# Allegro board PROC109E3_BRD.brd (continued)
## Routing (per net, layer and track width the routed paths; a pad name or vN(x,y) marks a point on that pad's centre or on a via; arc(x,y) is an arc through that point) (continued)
VSYS_3V3_CT: length 2.7
  BOTTOM w0.254: U27.4 17.24,58.7 C81.1
VSYS_3V3_FB: length 4.4
  TOP w0.254: U10.2 43.93,42.61 43.92,42.61 43.92,41.17 R77.1 R80.2 C40.2
VSYS_3V3_R: length 3.9
  TOP w0.508: 48.11,50.16 48.38,49.89 R35.2 48.38,48.38 47.6,47.6 C26.1
VSYS_3V3_SENSE: length 6.2
  BOTTOM w0.135: U27.9 19.8,53.58 20.35,53.04 20.35,51.44 21.3,50.48 R201.1 R195.1
VSYS_3V3_SW: length 4.8
  TOP w0.254: U10.6 44.43,45.08 44.85,45.51
  TOP w0.762: 44.85,45.51 L1.1
VSYS_5V0: length 100.5
  TOP w0.254: U21.7 49.64,30.4 C51.1 ; 32.72,23.7 32.7,23.69 U23.8 ; C25.1 43.93,45.64 U10.7 ; U23.7 32.78,23.19
  TOP w0.305: 122.6,43.45 122.17,43.02 C123.1 121.56,42.47 v1(121.36,42.27)
  TOP w0.381: R11.1 v1(12.05,55.71) ; R85.2 43.11,38.55 v1(43.18,38.48) ; v1(16.54,49.48) 17.11,48.9 17.11,41.17 15.57,39.62 12.7,39.62 11.68,40.64 8.64,40.64 6.73,38.73 R86.1 ; R117.1 34.97,24.99 v1(34.54,24.56)
  TOP w0.508: U14.1 50.36,38.72 49.94,39.14 ; v1(100.5,15.2) R161.2 v1(99.69,16)
  TOP w0.762: J9.1 137.27,15.11 131.34,21.03 129.08,21.03 127.36,22.76 127.36,40.41 124.32,43.45 122.6,43.45
  BOTTOM w0.203: U33.4 121.62,42.01 v1(121.36,42.27)
  BOTTOM w0.254: U27.14 16.24,51.05 16.38,50.91 C91.1 16.38,49.63 v1(16.54,49.48) ; v1(146.89,12.47) C269.1 146.26,12.47 U46.15
  BOTTOM w0.33: v1(163.42,22.66) R270.1 v1(164.19,23.46) ; v1(65.53,23.24) 65.56,23.27 R262.1
  BOTTOM w0.381: v1(16.54,49.48) 15.14,48.08 13.64,48.08 13.09,47.53 12.36,47.53 12.07,47.24 R211.2 ; v1(23.27,52.11) 23.2,52.04 R188.1 ; R171.2 9.28,58.49 v1(12.05,55.71)
  BOTTOM w0.508: R281.1 v1(152.98,14.38) ; R280.1 v1(154.79,14.38) ; R272.1 v1(156.51,20.73) ; R279.1 v1(156.51,14.38) ; R274.1 v1(152.98,20.73) ; R273.1 v1(154.79,20.73)
  vias: v1(32.26,24.59) v1(33.27,24.56) v1(33.27,23.6) v1(34.54,23.6) v1(35.89,24.56) v1(35.89,23.6) v1(35.92,22.66) v1(37.16,24.56) v1(37.16,23.6) v1(37.19,22.66) v1(39.98,48.64) v1(39.98,47.37) v1(39.98,46.1) v1(39.98,44.83) v1(41.25,48.64) v1(41.25,47.37) v1(41.25,46.1) v1(41.25,44.83) v1(42.52,48.64) v1(42.52,47.37) v1(42.52,46.1) v1(42.52,44.83) v1(45.7,33.35) v1(45.7,32.08) v1(45.7,30.81) v1(45.7,29.54) v1(46.84,37.03) v1(46.89,39.57) v1(46.86,38.48) v1(46.97,33.35) v1(46.97,32.08) v1(46.97,30.81) v1(46.97,29.54) v1(48.16,39.57) v1(48.24,33.35) v1(48.24,32.08) v1(48.24,30.81) v1(48.24,29.54)
VSYS_5V0_CT: length 2.4
  TOP w0.203: U23.6 32.75,22.69 33.02,22.42 C69.1
VSYS_5V0_ON: length 33.6
  TOP w0.254: v1(28.93,22.61) 29.01,22.68 29.06,22.68 29.06,22.69 U23.3 ; v1(17.15,34.17) LD9.1 16.54,34.8 16.27,35.06 U15.4
  L03_SIG1 w0.203: v1(28.93,22.61) 24.08,22.61 23.39,23.29 23.39,26.21 22.81,26.8 14.73,26.8 13.87,27.66 13.87,34.54 14.71,35.38 15.94,35.38 v1(17.15,34.17)
VUSB_5V0: length 55.4
  TOP w0.135: v1(15.12,27.46) 23.04,27.46 24.21,26.29
  TOP w0.178: 10.26,27.79 U20.12
  TOP w0.254: U15.5 15.91,36.06 16.07,36.22 C42.1 ; U23.2 29.04,23.19 28.88,23.34 ; 10.26,27.79 10.21,27.84 C57.1 9.3,28.37 v1(9.3,28.42) ; 28.42,23.14 28.42,22.31 28.68,22.06 29.07,22.06 29.2,22.19 U23.4 ; U23.1 29.02,23.69
  TOP w0.33: v1(17.27,36.22) 16.56,36.22 C42.1 ; R110.2 15.12,30.15 14.79,30.48 v1(14.63,30.48)
  TOP w0.381: R113.2 v1(15.12,27.46) ; v1(4.34,26.8) 4.29,26.75 v1(3.07,26.75) v1(1.8,26.75) ; v1(10.19,31.57) 10.55,31.94 R105.2 R106.2 ; v1(17.27,36.22) 17.71,35.78 R94.1
  L03_SIG1 w0.508: v1(9.3,28.42) 9.3,30.68 v1(10.19,31.57)
  L04_PWR1 w0.381: v1(17.27,36.22) 12.29,36.22 10.19,34.11 v1(10.19,31.57)
  L04_PWR1 w0.508: v1(4.34,26.8) 7.67,26.8 v1(9.3,28.42)
  BOTTOM w0.33: C226.1 3.81,27.3
  BOTTOM w0.381: v1(15.12,27.46) 14.63,27.95 v1(14.63,30.48) 11.28,30.48 v1(10.19,31.57)
WDI: length 3.1
  TOP w0.135: R9.2 v1(13.84,56.62)
  BOTTOM w0.135: U27.20 13.97,55.08 13.84,55.21 v1(13.84,56.62)
WDO: length 2.3
  TOP w0.135: R11.2 13.09,54.51 v1(13.49,54.12)
  BOTTOM w0.135: U27.19 13.95,54.58 v1(13.49,54.12)
XDS110_DEBUG_ID4: length 3.7
  TOP w0.135: R98.1 v1(20.5,30.51)
  BOTTOM w0.135: v1(20.5,30.51) 21.21,29.79 21.21,29.01 21.1,28.9 U37.63
XDS110_DEBUG_ID5: length 3.6
  TOP w0.135: R99.1 v1(22.05,30.51)
  BOTTOM w0.135: U37.62 21.5,29.96 v1(22.05,30.51)
XDS110_DEBUG_ID6: length 4.3
  TOP w0.135: R100.1 v1(23.52,30.51)
  BOTTOM w0.135: U37.61 21.9,29.34 23.07,30.51 v1(23.52,30.51)
XDS110_DEBUG_ID7: length 5.3
  TOP w0.135: R101.1 v1(24.99,30.51)
  BOTTOM w0.135: v1(24.99,30.51) 24.46,29.97 23.11,29.97 22.3,29.16 U37.60
XDS110_EMU0: length 7.8
  TOP w0.135: U16.8 28.51,33.64 29.06,33.1 29.06,30.06 29.26,29.86 R109.1 v1(29.84,29.18)
  BOTTOM w0.135: U37.42 29.5,29.05 29.64,29.18 v1(29.84,29.18)
XDS110_EMU1: length 12.2
  TOP w0.135: U16.1 31.62,33.64 32.03,33.23 32.03,29.03 31.5,28.5 29.06,28.5 v1(28.37,29.18) R108.1
  BOTTOM w0.135: v1(28.37,29.18) 28.93,29.18 29.1,29.01 U37.43
XDS110_PROG_STAZ1: length 35.2
  TOP w0.135: R114.2 v1(6.5,27.58)
  L03_SIG1 w0.121: v1(33.38,40.69) 32.57,39.88 20.29,39.88 19.43,39.01 16.18,39.01 7.16,30 7.16,28.24 v1(6.5,27.58)
  BOTTOM w0.135: v1(33.38,40.69) 34.6,40.69 U37.4
XDS110_PROG_STAZ2: length 36.8
  TOP w0.135: v1(6.25,30.58) 5.82,30.16 R111.2
  L03_SIG1 w0.121: v1(35.83,41.09) 35.74,41.17 33.12,41.17 32.09,40.14 19.92,40.14 19.05,39.27 14.69,39.27 8.61,33.19 8.61,32.94 v1(6.25,30.58)
  BOTTOM w0.135: v1(35.83,41.09) 35.82,41.09 U37.3
XDS110_TCK: length 44.4
  TOP w0.135: v1(70.33,24.21) 70.04,23.91 U25.13
  L03_SIG1 w0.121: v1(70.33,24.21) 69.91,24.62 68.52,24.62 67.23,25.91 66.31,25.91 64.62,27.6 64.62,28.41 62.22,30.8 50.66,30.8 48.9,29.04 32.91,29.04 v1(32.79,29.16)
  BOTTOM w0.135: U37.35 32.3,28.91 32.56,29.16 v1(32.79,29.16)
XDS110_TDI: length 49.3
  TOP w0.135: U25.12 v1(70.69,21.01)
  L03_SIG1 w0.121: v1(70.69,21.01) 70.69,21.72 69.52,22.89 68.97,22.89 64.34,27.52 64.34,28.33 62.81,29.86 50.18,29.86 48.09,27.77 39.29,27.77 38.76,28.3 31.65,28.3 v1(30.76,29.18)
  BOTTOM w0.135: U37.38 31.1,28.84 v1(30.76,29.18)
XDS110_TDO: length 50.6
  L03_SIG1 w0.121: v1(30.76,30.1) 30,30.1 29.18,29.29 29.18,26.54 29.59,26.14 30.17,26.14 30.45,26.42 30.45,26.95 31.16,27.66 37.42,27.66 38.39,26.69 44.13,26.69 45.04,25.78 59.59,25.78 60.78,24.59 v1(60.78,21.34)
  BOTTOM w0.135: U42.7 65.52,20.57 65.27,20.32 64.43,20.32 64.14,20.32 63.11,21.34 v1(60.78,21.34) ; U37.37 31.5,29.36 v1(30.76,30.1)
XDS110_TMS: length 46.8
  TOP w0.135: v1(71.48,24.23) 71.34,24.09 U25.11
  L03_SIG1 w0.121: v1(71.48,24.23) 70.74,24.97 68.63,24.97 67.34,26.26 66.32,26.26 64.87,27.71 64.87,28.51 62.33,31.06 50.21,31.06 49.28,30.12 45.11,30.12 44.28,29.3 33.49,29.3 v1(32.72,30.07)
  BOTTOM w0.135: U37.36 31.9,29.26 v1(32.72,30.07)
XDS110_TRST#: length 53.3
  TOP w0.135: U25.10 71.99,21.56 v1(72.01,21.54)
  L03_SIG1 w0.121: v1(72.01,21.54) 70.87,20.4 70,20.4 69.26,21.14 69.26,22.18 64.06,27.38 64.06,28.24 62.7,29.6 50.58,29.6 47.48,26.5 44.82,26.5 44.12,27.2 38.31,27.2 37.59,27.91 30.48,27.91 29.92,27.36 v1(29.92,26.64)
  BOTTOM w0.135: v1(29.92,26.64) 30.3,27.03 U37.40
XDS110_UART1_RXD: length 17.6
  L03_SIG1 w0.121: v1(39.65,23.77) 39.65,24.77 37.67,26.75 v1(33.88,26.75)
  BOTTOM w0.135: v1(39.65,23.77) 39.65,22.94 38.51,21.8 34.57,21.8 34.28,21.51 U45.13 ; v1(33.88,26.75) 33.33,26.75 33.1,26.98 U37.33
XDS110_UART1_TXD: length 17.6
  L03_SIG1 w0.121: v1(32.72,26.44) 32.87,26.29 37.57,26.29 38.38,25.48 v1(38.38,23.85)
  BOTTOM w0.135: U45.11 32.98,21.48 33.58,22.07 37.74,22.07 38.38,22.71 v1(38.38,23.85) ; v1(32.72,26.44) 32.7,26.45 U37.34
XDS110_VBUS_DET: length 21
  L03_SIG1 w0.121: v1(28.57,41.94) 24.82,45.69 v1(18.29,45.69)
  BOTTOM w0.135: v1(28.57,41.94) 29.11,41.4 33.1,41.4 33.58,41.89 U37.1
  BOTTOM w0.508: v1(18.29,45.69) 17.58,46.41 R212.1 R219.2
XDS_RBIAS: length 2.6
  BOTTOM w0.178: U37.59 22.7,26.83 23.05,26.48 23.05,25.71 R256.1
XDS_RESET#: length 6
  TOP w0.135: v1(17.73,33.43) 15.93,33.43 TP26.1
  BOTTOM w0.135: R246.2 v1(17.73,33.43) 17.73,31.88 18.12,31.49 U37.70
XDS_SHIELD:
  vias: v1(4.85,16.05) v1(4.85,14.78) v1(6.12,16.05) v1(6.12,14.78) v1(7.39,16.05) v1(7.39,14.78)
XDS_USB_D_N: length 35.3
  TOP w0.107: J20.2 6.52,21.73 6.73,21.52 7.59,21.52 7.73,21.66 U24.4 U24.7 9.5,21.66 9.64,21.52 10.06,21.52 v1(10.4,21.86)
  L03_SIG1 w0.102: v1(10.4,21.86) 10.73,21.53 11.27,21.53 12.24,22.51 12.24,34.34 14.5,36.6 15.85,36.6 16.73,37.49 17.22,37.49 17.75,38.02 18.36,38.02 18.9,37.49 20.47,37.49 20.86,37.89 20.86,38.67 v1(20.52,39.01)
  BOTTOM w0.107: U37.93 20.07,40.69 20.15,40.77 20.42,40.77 20.96,40.23 20.96,38.82 20.85,38.71 20.63,38.71 20.52,38.82 v1(20.52,39.01)
XDS_USB_D_P: length 35.3
  TOP w0.107: J20.3 6.52,21.08 6.73,21.29 7.59,21.29 7.73,21.16 U24.5 U24.6 9.5,21.16 9.64,21.29 10.06,21.29 v1(10.4,20.95)
  L03_SIG1 w0.102: v1(21.46,39.01) 21.12,38.67 21.12,37.78 20.57,37.24 18.79,37.24 18.26,37.77 17.86,37.77 17.33,37.24 16.84,37.24 15.95,36.35 14.61,36.35 12.5,34.24 12.5,22.4 11.37,21.28 10.73,21.28 v1(10.4,20.95)
  BOTTOM w0.107: v1(21.46,39.01) 21.19,39.29 21.19,40.33 20.52,41 20.1,41 20.02,41.09 U37.94
XDS_USB_ID: length 32.3
  TOP w0.135: U24.9 v1(9.66,22.66)
  TOP w0.178: v1(7.47,22.3) 7.82,22.66 U24.2 U24.9
  TOP w0.254: J20.4 v1(6.89,20.43)
  L03_SIG1 w0.121: v1(9.66,22.66) 8.71,23.61 8.71,26.21 7.87,27.05 6.1,27.05 5.56,27.58 5.56,30.68 14.25,39.37 v1(14.25,40.82)
  L03_SIG1 w0.127: v1(6.89,20.43) 7.47,21.01 v1(7.47,22.3)
  BOTTOM w0.135: R231.2 14.82,40.94 14.7,40.82 v1(14.25,40.82)
XDS_VREF: length 5.9
  BOTTOM w0.178: C129.1 36.63,38.69 U37.9
  BOTTOM w0.33: C129.1 C128.1 38.1,38.63
  BOTTOM w0.381: U36.3 39.64,39.13 39.38,38.88 R235.2 38.65,38.63 38.1,38.63
N17247526: length 1.4
  TOP w0.135: LD15.2 v1(175.98,8.43)
  BOTTOM w0.135: R282.2 v1(175.98,8.43)
N17247539: length 1.4
  TOP w0.135: LD14.2 v1(174.48,8.43)
  BOTTOM w0.135: R283.2 v1(174.48,8.43)
N17247599: length 1.4
  TOP w0.135: LD13.2 v1(172.98,8.43)
  BOTTOM w0.135: R284.2 v1(172.98,8.43)
N17247637: length 1.4
  TOP w0.135: LD12.2 v1(171.48,8.43)
  BOTTOM w0.135: R285.2 v1(171.48,8.43)
N29126233: length 2.6
  TOP w0.135: R67.1 24.79,44.32 24.16,44.96 SW4.11
N29126235: length 2.5
  TOP w0.135: SW4.12 24.18,46.23 24.59,45.82 R53.1
N29126237: length 2.4
  TOP w0.135: SW4.13 24.41,47.5 24.59,47.32 R48.1
N29126239: length 2.3
  TOP w0.135: SW4.14 24.41,48.77 24.46,48.82 R34.1
N29126243: length 2.7
  TOP w0.135: SW4.10 24,43.69 24.87,42.82 R70.1
N29126245: length 2.4
  TOP w0.135: SW4.15 24.46,50.04 24.74,50.32 R28.1
N29126269: length 2.5
  TOP w0.135: SW4.16 24.93,51.31 25.4,51.78 R17.1
N30174920: length 3.2
  BOTTOM w0.135: R179.2 R180.2 76.56,53.06 76.69,52.93 U31.2
N30212600: length 7.4
  TOP w0.135: LD2.1 165.76,61.47 164.78,60.48 v1(163.84,60.48)
  BOTTOM w0.135: Q5.2 Q5.1 ; Q5.1 163.84,59.18 Q5.8 163.84,58.53 Q5.6 Q5.5 ; Q5.1 v1(163.84,60.48)
N30212640: length 1.3
  TOP w0.135: v1(167.34,64.04) 167.34,63.4 LD1.2
  BOTTOM w0.135: R167.2 v1(167.34,64.04)
N30212699: length 7
  TOP w0.135: v1(168.66,60.48) 168.12,60.48 167.32,61.28 LD1.1
  BOTTOM w0.135: Q6.2 Q6.1 ; Q6.1 v1(168.66,60.48) ; Q6.1 168.66,59.18 Q6.8 168.66,58.53 Q6.6 Q6.5
N30213674: length 1.3
  TOP w0.135: v1(165.77,64.05) 165.77,63.41 LD2.2
  BOTTOM w0.135: v1(165.77,64.05) 165.77,63.39 R166.2
N30217069: length 3.6
  BOTTOM w0.178: U37.96 17.82,41.89 17.57,42.14 C114.1
  BOTTOM w0.33: C114.1 17.1,42.51 17.31,42.72 R222.1
N30217074: length 2.1
  BOTTOM w0.135: R231.1 17.85,41.49 U37.95
N30217111: length 1.4
  TOP w0.135: LD10.2 R111.1
N30217160: length 1.4
  TOP w0.135: LD11.2 R114.1
N30310219: length 2.7
  TOP w0.381: D3.3 35.95,28.29 R117.2 R118.1
N30339679: length 27.9
  TOP w0.135: R15.1 13.82,53.26 v1(14.71,52.37) 20.4,52.37 21.79,53.77 22.84,53.77 24,52.6 24.73,52.6 25.16,53.03 26.29,53.03 27.46,54.2 27.46,54.81 30,57.36 30,58.31 29.73,58.59 U1.1
  BOTTOM w0.135: v1(14.71,52.37) 14.18,52.37 13.84,52.71 13.84,53.82 14.1,54.08 U27.18 ; v1(14.71,52.37) 15.05,52.03 U27.15 ; v1(14.71,52.37) 14.69,52.39 U27.16
N30360253: length 14.6
  TOP w0.135: v1(143.37,24.84) 142.87,24.84 142.68,25.02 U19.48 ; TP25.1 142.68,34.75 v1(142.68,33.4) U19.13
  BOTTOM w0.135: v1(142.68,33.4) 140.69,31.41 140.69,26.57 142.42,24.84 v1(143.37,24.84)
N30371240: length 3.5
  BOTTOM w0.135: R258.2 180.75,35.6 J19.11
N30391563: length 2.3
  BOTTOM w0.135: R210.2 J18.11
N30391831: length 14
  TOP w0.135: U7.13 v1(142.68,52.45) 142.68,53.8 TP4.1 ; U7.48 142.68,43.98 142.8,43.87 v1(143.33,43.87)
  BOTTOM w0.135: v1(142.68,52.45) 140.77,50.54 140.77,46.43 v1(143.33,43.87)
N30573184: length 1.3
  TOP w0.135: R79.2 LD6.2
N30625746: length 12.9
  TOP w0.102: U18.B5 77.11,27.58 76.55,27.58 76.2,27.24
  TOP w0.135: 76.2,27.24 75.86,26.9 75.86,26.26 73.38,23.77 73.38,20.95 v1(72.36,19.94)
  BOTTOM w0.135: R271.2 v1(72.36,19.94)
N30693218: length 2.2
  TOP w0.135: v1(174.83,61.32) 174.81,61.33 LD3.3
  BOTTOM w0.135: R168.2 174.83,62.64 v1(174.83,61.32)
N30693408: length 2.8
  TOP w0.135: v1(172.62,61.34) 172.63,61.33 LD3.2
  BOTTOM w0.135: R169.2 173.63,61.87 173.09,61.34 v1(172.62,61.34)
N30703604: length 1.3
  TOP w0.135: LD7.2 R86.2
N30811240: length 7.9
  TOP w0.135: v1(175.58,60.14) 175.34,60.38 175.34,62.36 174.76,62.93 LD3.4
  BOTTOM w0.135: v1(175.58,60.14) Q9.5 Q9.6 176.23,58.87 Q9.8 175.9,58.5 176.23,58.17 Q9.1 Q9.2
N30811389: length 5.6
  TOP w0.135: v1(172.81,64.12) 173.27,63.66 LD3.1
  BOTTOM w0.135: Q4.2 Q4.1 172.06,62.82 Q4.8 172.06,63.47 Q4.6 ; Q4.6 v1(172.81,64.12) ; Q4.6 Q4.5
N30900913: length 6.5
  TOP w0.102: 76.05,32.86 U18.A15
  TOP w0.135: v1(72.7,33.03) 72.88,32.86 76.05,32.86
  BOTTOM w0.135: v1(72.7,33.03) 72.7,33.73 R244.1 72.7,35.08 R240.1
N30979572: length 1.8
  TOP w0.135: R162.2 70.31,16.18 70.04,16.45 U25.4
N31410611: length 1.3
  TOP w0.135: R91.2 LD8.2
N31410626: length 4.8
  TOP w0.135: Q3.2 Q3.1 1.71,34.09 Q3.8 1.71,34.74 Q3.6 ; Q3.6 1.71,35.89 1.72,35.9 LD8.1 ; Q3.6 Q3.5
N31458583: length 2.4
  TOP w0.135: R119.2 13.59,26.72 13.39,26.93 13.39,27.4 13,27.79 U20.3
N31483389: length 1.3
  TOP w0.254: LD9.2 R94.2
N32041451: length 3.1
  TOP w0.254: R31.2 58.05,49.98 58.48,49.54 U5.4

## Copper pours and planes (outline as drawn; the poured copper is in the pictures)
DGND on L03_SIG1 (solid shape): 168.03,13.81 168.09,13.9 168.2,13.88 169.97,12.12 169.97,11.59 169.9,11.5 169.79,11.52 168.03,13.28
DGND on L03_SIG1 (solid shape): 77.11,22.57 77.22,22.59 77.28,22.5 77.28,20.45 77.89,19.84 77.89,19.72 77.83,19.72 77.82,19.73 77.62,19.75 77.43,19.67 77.36,19.64 77.29,19.67 77.06,19.91 77.06,22.51
DGND on L03_SIG1 (solid shape): 12.92,34.16 12.97,34.17 13,34.12 13,28.87 13.46,28.41 13.46,27.49 14.56,26.39 15.47,26.39 15.56,26.33 15.54,26.22 13.02,23.7 13.02,22.66 12.94,22.57 12.88,22.56 12.85,22.61 12.85,34.09
DGND on L03_SIG1 (solid shape): 82.28,24.76 82.34,24.85 82.45,24.83 83.38,23.9 83.38,19.41 84.38,18.41 85.32,18.41 85.39,18.38 85.43,18.31 85.43,18.27 85.44,18.23 85.42,18.14 85.34,18.1 84.53,18.1 82.28,20.35
DGND on L03_SIG1 (solid shape): 141.67,30.89 141.67,27.13 139.5,24.96 139.5,24.95 139.34,24.78 139.31,24.54 139.29,24.46 139.21,24.42 139.14,24.42 139.03,24.4 138.97,24.49 138.97,24.97 138.06,25.88 138.06,31.04 138.33,31.31 141.25,31.31
DGND on L03_SIG1 (solid shape): 12.01,19.42 12.12,19.44 12.18,19.34 12.18,18.31 13.56,16.94 13.58,16.83 13.48,16.76 12.8,16.76 12.17,16.14 12.17,8.88 12.71,8.34 12.73,8.23 12.63,8.17 11.01,8.16 9.09,10.08 9.09,17.32 8.39,18.03 8.37,18.14 8.46,18.2 10.79,18.2
DGND on L03_SIG1 (solid shape): 65.24,28.09 65.3,28.18 65.41,28.16 65.66,27.91 65.97,27.91 66.04,27.88 66.07,27.82 66.32,27.48 66.73,27.58 66.8,27.61 66.87,27.58 68.54,25.91 68.57,25.83 68.53,25.76 68.51,25.74 68.44,25.71 68.37,25.74 67.49,26.63 66.47,26.63 65.24,27.86
DGND on L03_SIG1 (solid shape): 27.92,16.48 27.98,16.57 28.09,16.55 30.67,13.97 30.67,9.09 31.44,8.32 38.2,8.32 39.24,9.36 64.87,9.36 65.88,8.35 65.91,8.24 65.81,8.18 65.56,8.18 65.48,8.22 65.46,8.31 65.1,8.81 64.74,8.31 64.73,8.22 64.64,8.18 27.47,8.18 27.38,8.24 27.4,8.35 27.92,8.87
DGND on L03_SIG1 (solid shape): 22.46,21.94 22.52,22.03 22.63,22.01 26.82,17.83 26.84,17.72 26.75,17.65 24.16,17.65 23.6,17.1 23.6,16.76 21.81,16.76 21.23,16.18 21.2,16.2 20.86,16.27 20.56,16.13 20.52,16.12 20.49,16.13 20.39,16.2 20.27,16.25 20.24,16.28 20.24,16.31 20.01,16.89 19.4,16.86 19.36,16.9 19.33,16.98 19.36,17.05 20.16,17.86 20.56,17.86 20.56,17.86 21.69,17.86 22.46,18.63
DGND on L03_SIG1 (solid shape): 78.82,13.87 78.92,13.79 78.88,13.68 77.35,11.09 78.6,8.36 78.63,8.25 78.54,8.18 72.55,8.18 71.68,8.81 70.81,8.18 66.78,8.18 66.69,8.22 66.68,8.31 66.68,8.57 66.51,8.76 66.5,8.77 66.36,8.9 66.34,9.02 66.44,9.08 69.01,9.08 70.6,10.67 70.71,10.69 70.77,10.6 72.33,10 71.73,11.56 71.64,11.62 71.66,11.73 73.79,13.87
DGND on L03_SIG1 (solid shape): outline of 406 points within 68.09,15.87 78.44,26.09
DGND on TOP: 50.8,46.28 50.68,46.16 50.68,45.78 50.5,45.6 49.77,45.6 49.76,45.59 46.97,45.59 46.59,45.97 46.59,46.86 46.33,47.12 45.83,47.12 45.7,46.99 45.7,45.21 45.06,45.21 44.68,44.83 44.68,43.82 44.57,43.7 39.63,43.7 39.37,43.43 39.37,40.77 39.62,40.51 42.42,40.51 42.86,40.96 42.86,42.73 43.31,43.18 44.35,43.18 44.35,40.84 44.56,40.64 45.49,40.64 46.2,41.35 53.39,41.35 53.8,41.76 53.8,45.8 53.31,46.28
DGND on TOP: 48.74,36.88 49.57,36.88 50.14,37.45 55.36,37.45 55.5,37.59 55.5,37.91 55.32,38.09 54.83,38.09 54.82,38.08 50.02,38.08 49.53,37.59 48.76,37.59 48.67,37.5 48.67,36.96
DGND on TOP: 100.22,55.34 97.99,55.34 97.79,55.54 97.79,56.92 97.97,57.1 100.2,57.1 100.31,56.99 100.31,55.43
DGND on TOP: 74.68,40.52 74.68,39.97 75.19,39.45 75.53,39.45 76.48,38.51 76.48,38.14 76.65,37.97 76.87,37.97 76.96,38.06 76.96,39.8 76.24,40.52
DGND on TOP: 4.85,19.89 4.85,19.27 5.56,18.56 7.63,18.56 8.36,17.83 10.19,17.83 10.46,18.11 10.46,19.8 10.17,20.09 5.05,20.09
DGND on TOP: 72.95,39.87 72.95,37.63 73.37,37.21 74.78,37.21 76.76,35.23 77.06,35.23 77.52,35.69 77.52,35.94 77.01,36.45 76.71,36.45 74.69,38.47 74.26,38.47 73.52,39.21 73.52,39.87
DGND on TOP: 110.81,53.16 118.7,53.16 119.32,52.55 119.32,46.3 118.79,45.77 110.92,45.77 110.43,46.26 110.43,52.78 ; 1 cut-out
DGND on BOTTOM: 78.03,26.44 78.12,26.34 78.12,23.9 78.29,23.74 78.29,22.31 78.23,22.25 76.45,22.25 76.17,22.53 76.17,25.29 77.32,26.44
DGND on BOTTOM: 86.33,34.34 89.03,34.34 89.23,34.14 89.63,34.14 89.74,34.03 89.74,33.57 89.73,33.56 89.73,32.96 89.48,32.72 88.75,32.72 88.44,33.02 88.44,33.32 88.29,33.48 86.64,33.48 86.31,33.15 86.26,33.15 85.78,33.63 85.78,33.78
DGND on BOTTOM: 31.11,13.74 33.78,13.74 33.96,13.92 33.96,16.31 34.39,16.74 38.33,16.74 38.46,16.86 38.46,18.36 38.35,18.47 36.37,18.47 35.86,18.97 35.86,20.8 35.7,20.97 31.63,20.97 30.35,22.25 24.76,22.25 24.26,21.74 24.26,16.55 24.65,16.15 28.7,16.15
DGND on BOTTOM: 83.69,32.56 83.69,31.7 83.79,31.6 84.96,31.6 85.24,31.88 85.24,32.05 85.12,32.18 85.12,32.87 85.04,32.94 84.73,32.94 84.61,32.82 84.61,32.69 84.53,32.61 83.74,32.61
DGND on BOTTOM: 37.67,38.28 37.92,38.02 37.92,37.39 37.67,37.13 35.76,37.13 35.66,37.24 35.66,38.2 35.74,38.28
DGND on BOTTOM: 127.95,36.45 129.41,36.45 129.67,36.7 129.67,40.45 129.48,40.64 127.66,40.64 127.52,40.5 127.52,39.92 127.15,39.55 127.15,39.16 127.75,38.57 127.75,36.64
DGND on BOTTOM: 11.39,33.44 12.43,33.44 12.84,33.03 12.84,30.99 12.97,30.86 14.61,30.86 14.78,31.03 14.78,31.4 14.66,31.53 13.5,31.53 13.39,31.65 13.39,33.99 13.21,34.16 11.44,34.16 11.24,33.97 11.24,33.59
DGND on BOTTOM: 86.12,35.82 86.76,36.47 89.05,36.47 89.36,36.78 89.36,39.04 89.13,39.27 86.13,39.27 85.67,38.81 85.67,35.88 85.73,35.82
DGND on BOTTOM: 81.74,43.82 81.74,42.19 81.79,42.14 81.79,40.41 82.19,40.01 82.19,38.67 80.9,37.37 80.9,37.01 80.98,36.93 82.07,36.93 82.19,36.8 82.19,36.22 82.37,36.04 83.26,36.04 83.36,36.14 83.36,37.82 83.19,38 83.19,39.05 82.96,39.27 82.96,41.78 83.79,42.62 83.79,43.64 83.52,43.91 81.83,43.91
DGND on BOTTOM: 81.98,26.71 83.24,26.71 83.27,26.67 83.27,23.14 83.64,22.77 83.64,22.45 83.49,22.3 81.89,22.3 81.79,22.4 81.79,26.52
DGND on BOTTOM: 86.41,24.89 86.32,24.97 86.32,26.23 86.58,26.49 87.99,26.49 88.14,26.34 88.14,25.03 87.99,24.89
DGND on BOTTOM: 89.08,28.98 89.49,28.57 90.74,28.57 90.86,28.45 90.86,28.07 90.7,27.91 87.05,27.91 86.9,28.06 86.9,28.85 87.03,28.98
DGND on BOTTOM: 7.32,18.03 10.72,18.03 10.98,18.29 10.98,19.82 10.76,20.04 7.34,20.04 7.04,19.74 7.04,18.31
DGND on BOTTOM: 73.63,34.07 75.9,34.07 76.02,34.19 76.02,34.63 75.82,34.83 73.62,34.83 73.56,34.77 73.56,34.14
DGND on BOTTOM: 78.55,37.6 78.55,39.87 78.44,39.98 73.13,39.98 72.85,39.7 72.85,37.63 72.92,37.56 73.46,37.56 73.71,37.3 75.01,37.3 75.31,37.61 77.72,37.61 77.88,37.45 77.88,35.1 78,34.98 78.23,34.98 78.36,35.1 78.36,37.41
DGND on BOTTOM: 1.02,64.52 184.39,64.52 184.39,8.16 175.61,8.16 175.64,8.21 175.63,8.27 175.6,8.36 175.6,8.45 175.57,8.53 175.5,8.56 175.36,8.56 175.36,9.64 175.32,9.71 175.25,9.74 175.21,9.74 175.13,9.71 175.1,9.64 175.1,8.56 174.96,8.56 174.89,8.53 174.86,8.45 174.85,8.36 174.82,8.27 174.82,8.21 174.84,8.16 174.12,8.16 174.14,8.21 174.13,8.27 174.1,8.36 174.1,8.45 174.07,8.53 174,8.56 173.86,8.56 173.86,9.64 173.82,9.71 173.75,9.74 173.71,9.74 173.63,9.71 173.6,9.64 173.6,8.56 173.46,8.56 173.39,8.53 173.36,8.45 173.35,8.36 173.33,8.27 173.32,8.21 173.34,8.16 172.62,8.16 172.64,8.21 172.63,8.27 172.61,8.36 172.6,8.45 172.57,8.53 172.5,8.56 172.36,8.56 172.36,9.64 172.33,9.71 172.25,9.74 172.21,9.74 172.14,9.71 172.1,9.64 172.1,8.56 171.96,8.56 171.89,8.53 171.86,8.45 171.86,8.36 171.83,8.27 171.82,8.21 171.85,8.16 1.99,8.16 2.02,8.24 1.98,8.31 1.56,8.69 1.2,9.13 1.09,9.18 1.02,9.08 ; 101 cut-outs
DGND on L02_GND1: 184.22,64.48 184.34,62.13 184.34,54.49 179.84,54.49 179.84,55 177.98,56.86 174.08,56.86 173.85,56.63 173.85,42.61 171.1,39.86 168.29,39.86 167.93,39.5 167.93,37.42 168.31,37.04 176.06,37.04 178.47,39.45 184.33,39.45 184.33,32.87 180.27,32.87 180.04,33.1 180.04,34.22 179.28,34.99 174.67,34.99 173.86,34.18 173.86,21.28 170.1,17.52 170.1,15.27 173.01,15.27 173.93,14.35 175.85,14.35 177.9,16.4 177.9,17.21 178.42,17.73 183.91,17.73 183.91,15.46 180.97,12.52 180.97,8.22 9.95,8.22 8.84,9.33 8.84,16.37 6.16,19.04 4.93,19.04 4.37,19.61 4.37,22.07 4.95,22.66 6.08,22.66 7.16,23.74 7.16,25.7 6.91,25.96 1.36,25.96 1.11,26.21 1.11,64.48 1.11,63.7 1.18,63.6 1.29,63.64 1.62,64.02 2,64.35 2.04,64.41 2.03,64.48
DGND on L05_GND2: 27.77,8.15 27.48,8.43 27.48,15.54 27.23,15.8 24.43,15.8 23.63,16.6 22.19,16.6 20.75,15.16 15.67,15.16 15.39,15.45 15.39,15.95 15.04,16.31 8.9,16.31 6.74,18.47 5.68,18.47 4.11,20.03 4.11,22.4 4.37,22.66 6.65,22.66 7.16,23.16 7.16,25.7 6.91,25.96 1.36,25.96 1.15,26.17 1.15,63.32 2.23,64.4 184.33,64.4 184.33,53.14 180.72,53.14 179.87,53.99 179.87,54.97 177.98,56.86 174.08,56.86 173.85,56.63 173.85,42.61 171.1,39.86 168.29,39.86 167.93,39.5 167.93,37.42 168.31,37.04 176.06,37.04 178.51,39.49 184.33,39.49 184.33,32.87 180.04,32.87 180.04,34.22 179.28,34.99 174.67,34.99 173.86,34.18 173.86,21.28 170.1,17.52 170.1,15.27 173.01,15.27 173.93,14.35 175.85,14.35 177.9,16.4 177.9,17.21 178.47,17.77 184.29,17.77 184.29,14.7 180.85,11.25 180.85,8.15 ; 2 cut-outs
VBUS_TYPEC on TOP: 19.64,18.49 19.32,18.81 19.32,19.79 19.11,19.99 17.66,19.99 17.27,19.61 17.27,18.68 17.19,18.6 15.31,18.6 15.11,18.8 15.11,21.34 15.11,21.34 15.11,25.87 15.58,26.33 21.03,26.33 21.63,25.73 21.63,22.2 21.48,22.05 21.48,20.8 20.99,20.31 20.99,19.18 20.3,18.49
VBUS_TYPEC on BOTTOM: 17.31,20.45 17.31,19.57 17.7,19.18 19.3,19.18 19.42,19.3 19.42,24.1 19.71,24.38 20.9,24.38 22.66,22.63 22.66,17.71 21.06,16.11 15.39,16.11 14.1,17.4 14.1,20.32 14.48,20.7 17.05,20.7
VBUS_TYPEC on L03_SIG1: 15.11,21.96 15.12,21.97 15.12,24.81 16.63,26.33 21.44,26.33 21.83,25.94 21.83,18.89 21.43,18.5 20.3,18.5 20.3,18.49 15.46,18.49 15.11,18.85
VBUS_XDS_USB on TOP: 4.8,22.78 4.8,22.25 4.93,22.12 6.55,22.12 7.51,23.09 10.18,23.09 10.36,23.27 10.36,24.08 10.08,24.36 7.09,24.36 6.39,23.66 5.68,23.66
VBUS_XDS_USB on BOTTOM: 12.21,32.36 12.21,32.77 12.09,32.89 11.4,32.89 11.3,32.79 10.54,32.79 10.44,32.89 10.44,34.09 10.31,34.21 9.04,34.21 8.91,34.08 8.91,32.28 8.89,32.26 8.89,30.44 10.57,28.77 10.57,25.68 9.17,24.28 7.62,24.28 7.37,24.03 7.37,23.21 7.55,23.03 9.95,23.03 11.95,25.03 11.95,29.12 9.7,31.37 9.7,31.81 9.99,32.11 11.12,32.11 11.38,32.36
VCC3V3_TA on TOP: 10.03,55.4 11.25,55.4 11.51,55.14 11.51,47.17 11.25,46.91 10.03,46.91 9.78,47.17 9.78,55.14
VCC3V3_TA on TOP: 5.34,42.29 5.34,42.78 5.84,43.28 5.84,43.9 5.63,44.12 4.01,44.12 3.53,43.64 3.53,41.79 3.72,41.61 5.13,41.61 5.49,41.25 8.05,41.25 8.26,41.45 8.26,41.78 8.05,41.99 5.65,41.99
VCC3V3_TA on TOP: 25.98,52.07 25.98,42.44 26.19,42.24 26.59,42.24 26.72,42.37 26.72,52.14 26.7,52.16 26.07,52.16
VCC3V3_TA on TOP: 29.69,54.19 29.69,52.76 29.16,52.22 28.4,52.22 28.19,52.02 28.19,51.38 28.27,51.31 29.83,51.31 30.14,51.61 30.1,51.61 30.46,51.97 30.46,52.1 30.56,52.2 30.56,52.91 31.32,53.68 31.32,54.16 31.16,54.32 29.82,54.32
VCC3V3_TA on BOTTOM: 7.24,25.78 7,26.03 7,27.7 6.38,28.32 6.38,30.1 6.17,30.31 6.17,33.91 5.31,34.77 5.31,35.89 5.56,36.14 7.98,36.14 8.13,35.99 8.13,33.81 8.13,30.98 7.29,30.14 7.29,28.75 7.95,28.09 9.44,28.09 9.87,27.66 9.87,25.85 9.8,25.78
VCC3V3_TA on BOTTOM: 11.68,55.21 11.68,48.06 11.73,48.01 12.4,48.01 12.71,48.32 12.71,54.91 12.36,55.26 11.73,55.26
VCC3V3_TA on BOTTOM: 22.23,54.48 22.23,53.16 22.38,53.01 22.96,53.01 23.06,53.11 23.06,53.9 23.35,54.19 24.69,54.19 24.73,54.23 24.73,54.79 24.69,54.83 23.08,54.83 22.83,54.58 22.33,54.58
VCC3V3_TA on L03_SIG1: 3.05,45.78 3.05,33.73 4.09,32.69 6.71,32.69 7.72,33.71 7.72,35.46 6.02,37.16 6.02,43.99 7.19,45.16 7.57,44.78 15.6,44.78 17.46,46.63 25.49,46.63 27.15,48.29 29.4,48.29 30.35,49.25 30.35,53.31 28.52,55.14 23.79,55.14 20.6,51.95 13.07,51.95 12.4,52.63 12.4,55.32 11.89,55.83 10.68,55.83 6.83,51.98 6.83,49.57 ; 3 cut-outs
VCC3V3_XDS on TOP: 14.17,34.67 14.17,31.45 15.65,29.98 15.65,28.02 15.7,27.96 23.3,27.96 24.12,27.14 29.02,27.14 29.71,26.45 33.25,26.45 35.64,28.83 38.53,28.83 39.5,29.79 39.5,34.82 37.97,36.35 22.11,36.35 20.43,34.67 ; 3 cut-outs
VCC3V3_XDS on TOP: 18.08,37.87 17.5,38.46 17.5,46.47 18.04,47.01 24.03,47.01 24.03,46.43 24.26,46.43 24.67,46.02 24.81,46.02 24.81,46.44 26.05,46.44 26.05,46.7 24.81,46.7 24.81,47.01 37.75,47.01 38.35,46.4 38.35,38.13 38.1,37.87 ; 4 cut-outs
VCC3V3_XDS on BOTTOM: 25.16,26.92 26.22,26.92 26.42,26.72 26.42,26.16 26.16,25.91 25.18,25.91 25.04,26.05 25.04,26.79
VCC3V3_XDS on BOTTOM: 35.8,40.44 36.73,40.44 36.91,40.26 36.91,39.19 36.65,38.94 35.78,38.94 35.66,39.06 35.66,40.3
VCC3V3_XDS on BOTTOM: 36.5,30.39 36.34,30.23 35.86,30.23 35.53,30.55 35.53,32.84 35.71,33.02 36.32,33.02 36.5,32.84
VCC3V3_XDS on BOTTOM: 14.02,32.48 14.66,32.48 15.01,32.13 16.51,32.13 16.6,32.04 17.24,32.04 17.36,32.17 17.36,32.7 17.27,32.8 16.22,32.8 16.13,32.89 16.13,34.68 16.01,34.8 14.1,34.8 13.9,34.6 13.9,32.59
VCC3V3_XDS on L03_SIG1: 13.64,33.98 13.64,29.13 15.19,27.58 20.42,27.58 20.83,27.99 22.66,27.99 23.62,27.03 23.62,22.3 26.34,19.58 35.99,19.58 36.49,19.08 39.1,19.08 40.17,20.15 59.02,20.15 59.34,20.48 59.34,24.27 58.96,24.65 40.01,24.65 38.38,26.29 38.38,32.72 38.23,32.87 38.23,39.29 36.93,40.59 34.06,40.59 33.13,39.66 24.17,39.66 21.39,36.88 16.54,36.88 ; 1 cut-out
VDD_1V1 on BOTTOM: 124.71,30.43 124.71,25.98 124.97,25.73 126.53,25.73 127.12,26.33 127.12,27.57 126.51,28.18 126.51,28.98 126.87,29.35 126.87,29.83 126.76,29.95 126.09,29.95 125.6,30.43
VDD_1V1 on L04_PWR1: 136.5,23.51 136.93,23.08 139.03,23.08 139.51,23.56 139.51,27.29 139.9,27.69 144.76,27.69 145.1,28.03 145.1,32.19 144.53,32.77 139.36,32.77 138.64,33.49 138.64,36.05 141.78,39.19 141.78,41.82 142.43,42.46 144.39,42.46 145.1,43.17 145.1,47.86 144.31,48.65 133.76,48.65 133.06,47.95 133.06,47 136.83,43.23 136.83,40.24 132.62,36.04 125.6,36.04 124.87,35.31 124.87,25.66 125.21,25.32 130.57,25.32 131.39,26.15 131.39,28.03 131.94,28.58 135.8,28.58 136.5,27.87
VDD_1V8 on TOP: 66.55,50.44 66.27,50.16 65.19,50.16 65.18,50.17 64.2,50.17 63.93,50.44 63.93,51.59 63.63,51.89 63.12,51.89 62.76,52.25 62.76,53.65 62.96,53.85 66.32,53.85 66.55,53.62
VDD_1V8 on BOTTOM: 91.87,33.27 93.57,33.27 93.83,33.02 93.83,28.04 93.52,27.74 91.62,27.74 91.37,27.99 91.37,30.83 91.74,31.19 91.74,33.14
VDD_1V8 on BOTTOM: 64.49,52.81 64.49,51.14 68.24,47.39 71.29,47.39 74.65,44.02 74.65,40.89 74.92,40.62 78.49,40.62 78.49,42.62 78.23,42.88 78.23,43.77 68.85,53.16 64.83,53.16
VDD_1V8 on BOTTOM: 68.12,31.8 69.52,31.8 69.77,31.55 69.77,25.2 69.45,24.87 68.82,24.87 68.34,25.34 68.34,30.51 67.87,30.99 67.87,31.55
VDD_1V8 on L04_PWR1: 91.36,27.25 91.36,30.76 87.73,34.39 87.73,38.15 86.18,39.7 86.18,39.88 86.11,39.95 83.91,39.95 82.08,38.13 79.32,38.13 76.69,40.76 76.69,42.3 77.18,42.79 78.07,42.79 78.28,42.58 78.28,41.48 80.44,39.32 81.46,39.32 83.24,41.1 89.83,41.1 90.84,40.1 90.84,35.78 93.62,32.99 93.62,24.21 93.24,23.83 90.15,23.83 87.99,21.66 87.99,20.19 87.38,19.58 70.38,19.58 67.21,22.76 67.21,25.85 69.88,25.85 70.15,25.58 70.15,24.77 73.53,21.39 85.7,21.39 87.48,23.16 87.48,23.37
VDD_1V8_R on TOP: 61.83,48.01 61.96,47.88 66.37,47.88 66.56,48.07 66.56,49.65 66.43,49.78 63.65,49.78 63.41,49.54 63.41,49.24 62.59,48.41 61.85,48.41 61.83,48.39
VDD_2V5 on BOTTOM: 143.87,47.14 145.14,47.14 145.39,46.89 145.39,44.02 145.14,43.76 143.87,43.76 143.61,44.02 143.61,46.89
VDD_2V5 on BOTTOM: 143.81,28.19 145.11,28.19 145.36,27.94 145.36,25.35 145.11,25.1 143.81,25.1 143.56,25.35 143.56,27.94
VDD_2V5 on BOTTOM: 124.71,36.7 124.71,41.15 125.6,41.15 126.09,40.66 126.76,40.66 126.87,40.55 126.87,40.17 126.51,39.81 126.51,38.9 127.1,38.31 127.1,36.85 126.57,36.32 125.09,36.32
VDD_2V5 on L03_SIG1: 144.17,50.14 147.5,50.14 148.13,49.5 148.13,25.45 147.5,24.81 144.19,24.81 143.37,25.64 143.37,34.06 142.26,35.17 125.27,35.17 124.84,35.6 124.84,38.63 124.99,38.78 141.39,38.78 143.69,41.07 143.69,49.66
VDD_CORE_0V85 on TOP: 60.41,35.18 54.97,35.18 54.77,34.98 54.77,31.06 54.85,30.99 55.62,30.99 55.94,31.31 55.94,31.45 56.17,31.67 60.32,31.67 60.57,31.92 60.57,35.02
VDD_CORE_0V85 on BOTTOM: 77.5,35.52 73.57,35.52 73.47,35.62 73.47,36.62 73.62,36.77 74.97,36.77 75.11,36.63 77.57,36.63 77.6,36.61 77.6,35.61
VDD_CORE_0V85 on BOTTOM: 79.12,26.42 80.78,26.42 80.95,26.25 80.95,22.83 81.15,22.63 81.15,22.41 81.01,22.27 79.14,22.27 78.96,22.44 78.96,26.26
VDD_CORE_0V85 on L03_SIG1: 78.82,34.95 78.82,26.95 85.65,26.95 85.65,34.95
VDD_CORE_0V85 on L04_PWR1: 84.2,36.15 83.5,36.86 54.89,36.86 54.23,36.2 54.23,26.74 70.32,26.74 74.41,22.64 78.68,22.64 78.82,22.5 78.82,22.01 81.57,22.01 84.2,24.64
VDD_CORE_0V85_R on TOP: 51.54,34.92 51.8,35.18 53.98,35.18 54.25,34.91 54.25,32.13 54.15,32.04 54.15,31.25 54.1,31.2 53,31.2 52.94,31.26 52.94,32.13 52.68,32.38 51.67,32.38 51.54,32.51
VDD_CORE_0V85_SW on TOP: 50.85,35.05 49.64,35.05 49.51,34.92 49.51,32.44 49.69,32.26 50.86,32.26 51,32.4 51,34.9
VDDA_1P8_USB0 on BOTTOM: 86.58,32.41 86.58,31.88 86.65,31.8 88.33,31.8 88.58,31.55 90.87,31.55 91.03,31.71 91.03,32.98 90.95,33.06 90.12,33.06 89.99,32.92 89.99,32.37 89.83,32.22 88.42,32.22 88.15,32.49 86.66,32.49
VDDA_1V8 on BOTTOM: 79.24,41.72 79.24,40.03 79.04,39.82 79.04,38 79.3,37.74 80.21,37.74 80.42,37.95 80.42,39.56 80.91,40.06 80.91,41.68 80.68,41.91 79.43,41.91
VDDA_PLL0 on BOTTOM: 90.72,30.67 90.72,29.22 90.57,29.07 89.83,29.07 89.3,29.6 87.27,29.6 87.16,29.72 87.16,30.1 87.26,30.2 88.25,30.2 88.82,30.77 90.62,30.77
VDDA_PLL1 on BOTTOM: 70.43,27.1 70.43,25.48 70.56,25.35 71.65,25.35 71.83,25.53 71.83,25.83 72.03,26.03 75.06,26.03 75.45,26.43 75.45,27.52 75.26,27.71 74.7,27.71 74.55,27.56 74.55,27.3 74.22,26.97 72.19,26.97 71.88,27.28 70.61,27.28
VDDA_PLL2 on BOTTOM: 70.36,31.62 70.36,30.34 70.48,30.21 71.95,30.21 72.52,30.78 73.13,30.78 73.23,30.89 73.23,31.55 73.03,31.75 70.48,31.75
VDDA_TEMP on BOTTOM: 70.48,29.06 70.48,27.99 70.66,27.81 71.81,27.81 72.47,28.47 73.18,28.47 73.3,28.6 73.3,29.06 72.82,29.54 70.97,29.54
VDDSHV_3V3 on BOTTOM: 83.74,39.28 84.67,39.28 84.84,39.12 84.84,35.69 84.58,35.43 83.74,35.43 83.67,35.51 83.67,39.2
VDDSHV_3V3 on BOTTOM: 83.31,29.01 83.31,27.84 84.35,27.84 84.35,29.01
VDDSHV_3V3 on BOTTOM: 73.62,32.82 74.7,32.82 74.96,33.07 77.42,33.07 77.57,32.92 77.57,32.03 77.1,31.56 75.18,31.56 74.93,31.3 74.93,30.66 75.08,30.51 77.95,30.51 78.64,29.82 78.64,29.16 78.56,29.08 78.28,29.08 78.05,29.31 78.05,29.51 77.9,29.67 77.22,29.67 76.81,29.26 76.81,26.67 76.68,26.54 76.08,26.54 75.98,26.64 75.98,27.8 74.26,29.52 74.26,31.12 73.53,31.85 73.53,32.73
VDDSHV_3V3 on BOTTOM: 84.25,26.46 85.68,26.46 85.89,26.24 85.89,24.47 85.85,24.51 85.85,22.34 85.61,22.1 84.58,22.1 84.12,22.56 84.12,26.32
VDDSHV_3V3 on L04_PWR1: 85.08,27.34 84.71,26.97 84.71,24.35 83.73,23.37 83.73,22.68 84.4,22.01 85.69,22.01 87.02,23.34 87.02,23.6 90.5,27.08 90.5,31.29 87.19,34.6 87.19,38.15 86.09,39.25 84.11,39.25 83.59,38.73 83.59,37.4 83.67,37.32 83.68,37.32 84.41,36.6 84.41,34.15 84.1,33.84 84.1,29.69 85.08,28.71
(no net) on TOP: outline of 86 points within 1.56,8.18 184.35,64.52 ; 122 cut-outs
(no net) on L03_SIG1: 11.01,8.16 9.09,10.08 9.09,17.32 6.62,19.79 6.62,23.2 7.16,23.74 7.16,25.7 6.91,25.96 1.36,25.96 1.2,26.12 1.2,63.41 2.25,64.47 184.15,64.47 183.88,64.19 183.88,54.58 180.25,54.58 177.98,56.86 174.08,56.86 173.85,56.63 173.85,42.61 171.1,39.86 168.29,39.86 167.93,39.5 167.93,37.42 168.31,37.04 176.06,37.04 178.87,39.85 181.46,39.85 181.46,34.37 183.25,34.37 183.74,33.88 183.91,33.88 183.91,33.01 180.19,33.01 180.19,34.07 179.28,34.99 174.67,34.99 173.86,34.18 173.86,21.28 169.96,17.38 169.96,15.7 170.84,14.82 176.39,14.82 179.75,18.19 180.97,18.19 180.97,8.18 15,8.18 ; 141 cut-outs
BP_3V3 on TOP (solid shape): 104.26,13.46 103.31,12.73 102.62,13.42 102.6,13.46 102.62,13.51 103.31,14.19
BP_3V3 on TOP: 101.12,14.4 101.12,12.4 105.28,12.4 105.28,14.4
BP_5V0 on TOP: 101.24,15.01 101.24,17.02 105.23,17.02 105.23,15.01
EQEP1_A on TOP (solid shape): 157.41,11.62 157.46,11.64 157.5,11.62 158.19,10.93 157.46,10.02 156.73,10.93
EQEP2_A on BOTTOM (solid shape): 157.41,17.97 157.46,17.99 157.5,17.97 158.19,17.28 157.46,16.37 156.73,17.28
ETH1_EARTH on TOP: 174.18,34.39 174.18,21.08 170.39,17.3 170.39,15.58 173.09,15.58 173.95,14.72 175.66,14.72 177.53,16.59 177.53,18.31 178.87,19.66 184.46,19.66 184.46,30.71 180.47,30.71 179.87,31.32 179.87,34.06 179.2,34.72 174.51,34.72
ETH1_EARTH on BOTTOM, L02_GND1, L03_SIG1, L04_PWR1, L05_GND2: 174.18,34.39 174.18,21.08 170.41,17.32 170.41,15.65 173.09,15.65 174.02,14.72 175.66,14.72 177.53,16.59 177.53,18.31 178.87,19.66 184.46,19.66 184.46,30.71 180.47,30.71 179.87,31.32 179.87,34.06 179.2,34.72 174.51,34.72
ETH2_EARTH on TOP: 174.19,56.65 174.08,56.54 174.08,42.34 171.33,39.59 168.52,39.59 168.13,39.2 168.13,37.69 168.47,37.35 175.96,37.35 179.19,40.58 184.51,40.58 184.51,53.16 179.97,53.16 179.87,53.26 179.87,54.77 177.98,56.65
ETH2_EARTH on BOTTOM, L02_GND1, L03_SIG1, L04_PWR1, L05_GND2: 174.54,57 174.08,56.54 174.08,42.34 171.33,39.59 168.52,39.59 168.14,39.21 168.14,37.69 168.47,37.36 175.98,37.36 179.19,40.58 184.51,40.58 184.51,52.81 184.39,52.68 180.45,52.68 179.87,53.26 179.87,54.76 177.62,57
USBC_SHIELD on TOP, L05_GND2: 13.11,8.83 12.81,9.13 12.81,15.88 13.06,16.13 14.97,16.13 15.35,15.75 15.35,14.73 15.73,14.35 21.32,14.35 21.82,14.86 21.82,15.88 22.08,16.13 23.98,16.13 24.24,16.38 24.24,16.83 24.42,17.02 27.03,17.02 27.28,16.76 27.28,9.15 26.96,8.83
USBC_SHIELD on BOTTOM: 13.1,8.83 12.81,9.13 12.81,15.88 13.06,16.13 14.97,16.13 15.35,15.75 15.35,14.73 15.73,14.35 21.32,14.35 21.82,14.86 21.82,15.88 22.08,16.13 23.6,16.13 24.08,15.65 24.08,14.45 24.54,14 27.42,14 27.7,13.72 27.7,9.3 27.24,8.83
USBC_SHIELD on L02_GND1: 13.1,8.84 12.81,9.14 12.81,15.88 13.06,16.13 13.86,16.13 14.77,15.22 14.77,14.47 15.11,14.12 21.51,14.12 22.15,14.76 22.15,15.77 22.5,16.13 23.98,16.13 24.24,16.38 24.24,16.83 24.42,17.02 27.03,17.02 27.28,16.76 27.28,9.19 26.93,8.84
USBC_SHIELD on L03_SIG1: 13.37,8.58 12.81,9.14 12.81,15.88 13.06,16.13 14.97,16.13 15.35,15.75 15.35,14.73 15.73,14.35 21.32,14.35 21.82,14.86 21.82,15.88 22.08,16.13 23.98,16.13 24.24,16.38 24.24,16.83 24.42,17.02 27.03,17.02 27.28,16.76 27.28,9.13 26.73,8.58
USBC_SHIELD on L04_PWR1: 13.11,8.83 12.81,9.13 12.81,15.88 13.06,16.13 14.97,16.13 15.35,15.75 15.35,14.73 15.73,14.35 21.32,14.35 21.82,14.86 21.82,15.88 22.08,16.13 23.98,16.13 23.99,16.14 26.61,16.14 27.14,15.61 27.14,9.01 26.96,8.83
VPP_1V8 on TOP: 53.24,39.77 53.24,38.68 53.44,38.48 54.84,38.48 55.12,38.76 56.62,38.76 56.72,38.86 56.72,40.36 56.44,40.64 55.32,40.64 54.61,39.93 53.39,39.93
VSYS_3V3 on TOP: 8.81,44.17 8.81,43.43 9.35,42.9 9.35,41.76 9.49,41.61 10.65,41.61 10.82,41.78 10.82,43.89 10.54,44.17
VSYS_3V3 on TOP: 31.7,53.03 31.7,51.74 31.75,51.69 32.26,51.69 32.44,51.51 34.85,51.51 35.08,51.74 35.08,53.31 34.93,53.45 32.12,53.45
VSYS_3V3 on TOP: 98.5,17.86 98.5,17.17 100.15,17.17 100.15,17.86
VSYS_3V3 on TOP: 56.32,45.11 54.44,46.99 50.55,46.99 50.27,46.71 50.27,46.42 50.08,46.23 49.27,46.23 49.2,46.3 49.2,50.47 49.87,51.14 54.95,51.14 57.71,48.39 60.04,48.39 60.18,48.25 60.18,47.88 60.05,47.75 59.56,47.75 59.44,47.62 59.44,45.38 59.16,45.11
VSYS_3V3 on TOP: 95.96,60.53 100.61,60.53 100.86,60.27 100.86,58.22 100.68,58.03 98.56,58.03 98.42,58.17 96.01,58.17 95.71,58.47 95.71,60.27
VSYS_3V3 on TOP: 139.57,36.68 140.18,36.68 140.39,36.48 140.39,33.7 140.25,33.57 139.51,33.57 139.32,33.76 139.32,36.42
VSYS_3V3 on TOP: 139.57,55.73 140.18,55.73 140.39,55.53 140.39,52.75 140.25,52.62 139.62,52.62 139.32,52.92 139.32,55.47
VSYS_3V3 on BOTTOM: 35.69,15.65 37.31,15.65 37.57,15.39 37.57,12.14 37.31,11.89 35.69,11.89 35.43,12.14 35.43,15.39
VSYS_3V3 on BOTTOM: 90.07,23.64 90.07,21.25 87.07,21.25 86.52,21.8 86.52,24.15 86.61,24.24 89.47,24.24
VSYS_3V3 on BOTTOM: 122.42,40.25 122.42,43.48 122.2,43.7 120.79,43.7 119.79,42.71 116.33,42.71 116.13,42.5 116.13,39.85 116.36,39.62 121.79,39.62
VSYS_3V3 on BOTTOM: 122.42,29.54 122.42,31.47 122.32,31.57 121.38,31.57 120.97,31.99 116.42,31.99 116.15,31.72 116.15,29.11 116.36,28.91 121.79,28.91
VSYS_3V3 on L04_PWR1: outline of 119 points within 1.11,8.13 184.29,64.47
VSYS_3V3 on L04_PWR1: 98.5,18.34 98.5,16.84 100.15,16.84 100.15,18.34
VSYS_3V3_R on TOP: 45.94,50.28 46.08,50.42 48.38,50.42 48.6,50.2 48.6,46.51 48.41,46.32 47.26,46.32 47.14,46.44 47.14,47.2 46.71,47.62 46.07,47.62 45.94,47.75
VSYS_3V3_SW on TOP: 45.14,50.29 43.92,50.29 43.79,50.16 43.79,47.68 43.98,47.5 45.15,47.5 45.29,47.64 45.29,50.14
VSYS_5V0 on TOP: 32.62,26.06 31.67,25.12 31.67,23.19 31.86,23.01 32.81,23.01 32.91,23.1 33.25,22.76 35.33,22.76 36.6,21.49 38.66,21.49 39.14,21.97 39.14,25.67 38.74,26.06
VSYS_5V0 on TOP: 45.34,29.21 44.96,29.59 44.96,36.84 45.85,37.73 45.85,39.01 46.71,39.88 51.63,39.88 51.85,39.66 51.85,38.65 51.73,38.53 48.65,38.53 48.32,38.2 48.32,35.42 48.86,34.88 48.86,32.68 49.76,31.78 49.76,29.47 49.41,29.47 49.15,29.21
VSYS_5V0 on TOP: 44.05,44.94 44.05,47.02 43.16,47.91 43.16,48.8 42.76,49.2 39.76,49.2 39.36,48.81 39.36,44.71 39.5,44.58 43.69,44.58
VSYS_5V0 on TOP: 120.83,44.32 120.83,42.11 120.93,42.01 121.56,42.01 121.84,42.29 124.19,42.29 125.46,41.03 125.46,22.4 127.38,20.47 130.22,20.47 136.06,14.64 136.06,12.55 136.47,12.14 138.56,12.14 138.73,12.32 138.73,14.48 129.55,23.66 129.55,43.38 128.43,44.5 121.01,44.5
VSYS_5V0 on TOP: 99.39,16.38 99.39,14.86 100.84,14.86 100.84,16.38
VSYS_5V0 on L04_PWR1: 41.96,15.06 37.44,15.06 36.08,16.42 36.08,18.82 32.01,22.9 32.01,39.73 27.4,44.35 27.23,44.35 22.63,48.95 12.42,48.95 11.58,49.79 11.58,57.1 11.96,57.48 23.88,57.48 29.68,51.69 41.64,51.69 44.94,48.39 44.94,45.97 49.25,41.66 51.16,41.66 52.68,40.13 52.68,23.7 65.53,23.7 70.15,19.08 88.04,19.08 88.19,18.92 149.42,18.92 153.25,22.76 160.1,22.76 161.72,24.38 164.87,24.38 165.56,23.7 165.56,16.87 167.09,15.34 167.11,15.34 170.36,12.1 170.36,8.84 169.77,8.26 73.32,8.26 67.16,14.41 42.61,14.41
VUSB_5V0 on TOP: 22.23,22.78 22.23,26.29 22.45,26.52 29.21,26.52 29.98,25.74 29.98,24.18 30.28,23.89 30.28,23.06 30.1,22.89 29.06,22.89 28.82,22.64 27.88,22.64 27.43,22.2 22.81,22.2
VUSB_5V0 on BOTTOM: 1.4,27.77 1.4,26.61 1.69,26.31 5.99,26.31 6.21,26.54 6.21,27.8 6.1,27.91 4.68,27.91 4.53,27.76 3.11,27.76 2.86,28.02 1.64,28.02
XDS_SHIELD on TOP, L04_PWR1, L05_GND2: 1.78,14.55 1.11,15.22 1.11,25.85 1.35,26.09 6.65,26.09 6.96,25.78 6.96,24.71 6.27,24.03 4.01,24.03 3.56,23.58 3.56,18.71 4.15,18.11 6.55,18.11 7.67,16.99 10.64,16.99 10.95,16.69 10.95,14.92 10.58,14.55
XDS_SHIELD on BOTTOM: 1.58,14.33 1.11,14.8 1.11,25.34 1.42,25.65 6.42,25.65 6.83,25.25 6.83,23.64 6.09,22.91 4.26,22.91 3.78,22.44 3.78,18.54 4.29,18.03 6.27,18.03 7.14,17.16 7.14,16.61 8.03,15.72 11.02,15.72 11.2,15.54 11.2,14.54 10.99,14.33
XDS_SHIELD on L02_GND1: 1.78,14.55 1.11,15.22 1.11,25.85 1.35,26.09 6.65,26.09 6.96,25.78 6.96,24.71 6.27,24.03 4.01,24.03 3.56,23.58 3.56,18.71 4.15,18.11 6.55,18.11 8.15,16.51 8.15,14.94 7.77,14.55
XDS_SHIELD on L03_SIG1: 1.78,14.55 1.11,15.22 1.11,25.85 1.35,26.09 6.65,26.09 6.96,25.78 6.96,24.71 6.27,24.03 4.01,24.03 3.56,23.58 3.56,18.71 4.15,18.11 6.55,18.11 7.67,16.99 8.23,16.99 8.43,16.79 8.43,14.88 8.1,14.55

Small or netless copper shapes (teardrops, artwork), in the pictures only: 526 on TOP, 432 on BOTTOM, 304 on L03_SIG1, 5 on L04_PWR1, 2 on L05_GND2

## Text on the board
Ref Des/Assembly Bottom: BOTTOM ASSEMBLY
Ref Des/Silkscreen Bottom: B | A | C | J1 | J3 | J4 | J2 | J5 | J8 | J7 | J6 | LP-AM243 | Development Kit | www.ti.com/launchpad | TEST AUTOMATION | FOR EVALUATION ONLY; | NOT FCC APPROVED FOR RESALE
User.Comments: BOARD NAME: | AM243x LP EVM | REV: | DATE: 19-11-21 | E3 | DESCRIPTION: | SHEET    OF 13 | PROC109 | SCALE: 1 | TEXAS INSTRUMENTS
Ref Des/Assembly Top: TOP ASSEMBLY
Ref Des/Silkscreen Top: XDS110,MAIN UART0 | A | MCU PORZ | BOOT MODE SEL | VBUS_TYPEC | MCU RESETZ | BRD PWR IN | VSYS_5V0 ON | VSYS_3V3 ON | VDDCORE_0V85 ON | VCC3V3_XDS | SOC_RESET_REQZ | VSYS_5V0 | VSYS_3V3 | MCU_RESETz | USER_INTn | VDD_1V8 | J1 | J3 | J4 | J2 | USER INTN | SOC_RESETSTATz | PORz_OUT | FSI | VDD_1V1 | VDD_2V5 | J8 | J6 | J5 | J7 | eQEP1 | MAIN UART1 | MCU UART0 | eQEP2 | MCAN0 | IND LEDS | PWR ERR | MCU_PORz | 21 | 1 | 20 | 40 | 5V0 | 3V3 | GND | 2 | 39 | 19 | 3 | 18 | 38 | 23 | 4 | 17 | 37 | 24 | 5 | 16 | 36 | 25 | 6 | 15 | 35 | 26 | 7 | 14 | 34 | 27 | 8 | 13 | 33 | 28 | VDD_CORE_0V85 | 9 | 32 | 12 | 29 | SoC_RESET_REQz | 11 | 30 | 10 | 31 | OSPI0 CLK | MCU_SAFTY_ERRz | MCU RESETSTATz | 60 | 80 | 61 | 41 | 42 | 79 | 59 | 43 | 78 | 58 | 63 | 44 | 77 | 57 | 64 | 45 | 76 | 56 | 65 | 46 | 75 | 55 | 66 | 47 | 74 | 54 | 67 | 48 | 73 | 53 | 68 | 49 | 72 | 52 | 69 | 51 | 50 | 70 | 71 | IND LED GREEN | PRG/CPSW RGMII2 | PRG/CPSW RGMII1 | IND LED RED | IND LED BCLR | ASSY | OPN#: LP-AM243 | PCB#: PROC109E3 | SL#
PAGE_OUTLINE: REVIEWED BY | APPROVED BY | LAYOUT BY | SIGNATURES | PA | ZA | AMB | 19-11-21 | DATE | SIZE | SCALE: | D | NONE | SHEET 1 OF 13 | PROC109E3 | Rev | TEXAS INSTRUMENTS | E3 | AM243x LP EVM
DIMENSION: 17. | FOR DETAILED STACK-UP, PROC109_STACK_UP.pdf SHALL BE REFERRED | ENSURE THAT UL REGISTERED E-FILE NUMBER SHALL BE PRINTED ON PCB SILKSCREEN.
User.10: R178 | R186 | R189 | R197 | R209 | R171 | C146 | C155 | R182 | R187 | Q8 | Y1 | R196 | R202 | R212 | R219 | R222 | R231 | C114 | R246 | D7 | U27 | C120 | C132 | D6 | R176 | R195 | C85 | D8 | R256 | Q7 | R191 | R170 | C240 | C268 | C129 | C151 | C180 | C191 | C192 | C184 | C135 | C144 | C163 | J2 | J1 | C134 | C141 | C203 | C133 | C140 | C145 | Q16 | R255 | R262 | C260 | C232 | U42 | C161 | FB6 | FB8 | R234 | FB9 | FB3 | R240 | R244 | C193 | C259 | R271 | C94 | C194 | FB2 | C234 | C244 | C250 | C255 | C227 | C126 | C239 | C247 | C251 | C254 | R183 | C116 | C235 | C245 | C249 | C253 | R208 | C237 | C246 | R261 | C206 | FB4 | R206 | FB7 | FB5 | U30 | C209 | C166 | R250 | J6 | J5 | U33 | U39 | R248 | R233 | U29 | C125 | C130 | C222 | R218 | R221 | R230 | R254 | R260 | C98 | C97 | C228 | C93 | C207 | C221 | R242 | C258 | R266 | C86 | C100 | C217 | C231 | C96 | C84 | C159 | C152 | U46 | C119 | R236 | C92 | C95 | C99 | R225 | C197 | C230 | C216 | C107 | C238 | R241 | R245 | R259 | R263 | R276 | Q14 | Q15 | Q10 | Q11 | Q12 | Q13 | R270 | C257 | Q6 | C83 | C261 | C264 | C115 | C127 | Q5 | C195 | C89 | Q4 | Q9 | R200 | R253 | C101 | C252 | U38 | R188 | U26 | U37 | U45 | U28 | U36 | C153 | R287 | C224 | FB1 | U31 | R286 | U40 | C248 | U32 | C87 | U34 | U43 | U35 | U44 | C202 | C160 | C158 | C165 | WHEN ACTUATOR IS OPENED | R251 | J15 | C226 | C243 | C263 | D5 | C79 | C170 | R211 | C131 | R249 | C208 | C91 | C182 | L3 | C154 | C181 | R201 | R175 | R177 | C266 | C242 | C104 | C105 | C102 | C88 | C121 | C262 | C128 | R235 | R224 | C171 | C169 | C189 | C168 | C167 | C210 | C162 | C201 | C214 | C148 | C188 | C200 | C215 | C172 | C147 | C187 | C199 | C175 | C212 | C186 | C173 | C211 | C185 | C150 | C196 | C149 | C213 | C179 | R238 | C108 | R237 | C110 | C117 | C118 | C225 | C241 | C142 | C236 | C136 | R181 | C139 | C138 | R180 | C223 | C137 | R179 | C233 | R239 | R217 | C204 | C156 | R216 | R194 | R207 | R193 | R215 | R192 | R214 | R205 | R213 | R204 | C90 | R203 | R190 | C124 | C220 | C123 | C219 | C122 | C218 | C111 | C183 | C229 | R232 | R247 | R269 | R268 | R229 | R228 | R267 | R184 | C113 | C256 | R185 | C270 | R227 | R275 | R226 | R265 | R264 | C269 | R274 | R281 | R280 | R273 | R257 | R252 | R279 | R272 | C112 | R223 | R220 | R243 | R278 | R277 | R173 | C267 | R210 | R258 | C265 | C164 | R172 | R167 | R166 | R285 | R169 | R284 | R165 | R174 | R283 | R168 | R282 | U41 | C82 | C81 | R199 | C80 | R198 | C190 | C174 | C143 | C198 | C178 | C177 | C176 | C157 | C109 | C103 | C106 | C205 | REV # | SCALE:NONE | SIZE | FILE NAME: | DESCRIPTION | REVISIONS | CCN # | DRAWING NO. | DDMMYY | DATE | OF | REV | AM243x LP EVM ASSEMBLY BOTTOM REV.E1 | SHEET | 02 | C | FY10XXXX5200X0X | *
User.14: LED102 | LED101 | J1 | J5 | J7 | S1 | J3 | C3 | C7 | R1 | C1 | R7 | R5 | Q2 | R2 | Q1 | R3 | R4 | MSP1 | C10 | C8 | TP110 | L1 | C4 | S3 | J4 | JP102 | S2 | J6 | J2 | C11 | C6 | C5 | C12 | C2 | J102 | J8 | C13 | R6 | J101
User.42: 06 | EDGE COUPLED STRIPLINE | EDGE COUPLED MICROSTRIP | L3 | L1,L6 | 4.75 | 5.3 | NA | 50 | L2 | L2,L5
User.45: BOARD NAME: | AM243x LP EVM | REV: | DATE: 15-09-21 | E3 | DESCRIPTION: | SHEET    OF 13 | PROC109 | SCALE: 1 | TEXAS INSTRUMENTS | FIGURE | SIZE | 8.0 | 16.0 | 36.0 | 40.0 | 44.0 | 46.0 | 66.0 | 32.0 | 126.0 | 48.0x22.0 | 48.0x24.0 | 68.0x34.0 | DRILL CHART: TOP to BOTTOM | ALL UNITS ARE IN MILS | TOLERANCE | +3.0/-3.0 | +2.0/-2.0 | PLATED | NON-PLATED | QTY | 1494 | 14 | 20 | 43 | 80 | 4 | 8 | 92 | 2
